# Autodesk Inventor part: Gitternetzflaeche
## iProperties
Created: 2005-09
Part Number: Gitternetzflaeche
Material: .
Document SubType Name: Modeling
Designer: rsc
Manufacturer: Standard
Standards Organization: Custom
Kanten: brechen
Oberflächen: Ra 3,2
Radien: 2
Toleranzen: ISO 2768 - m
Author: rsc
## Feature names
1. Sweeping1
2. Extrusion1
